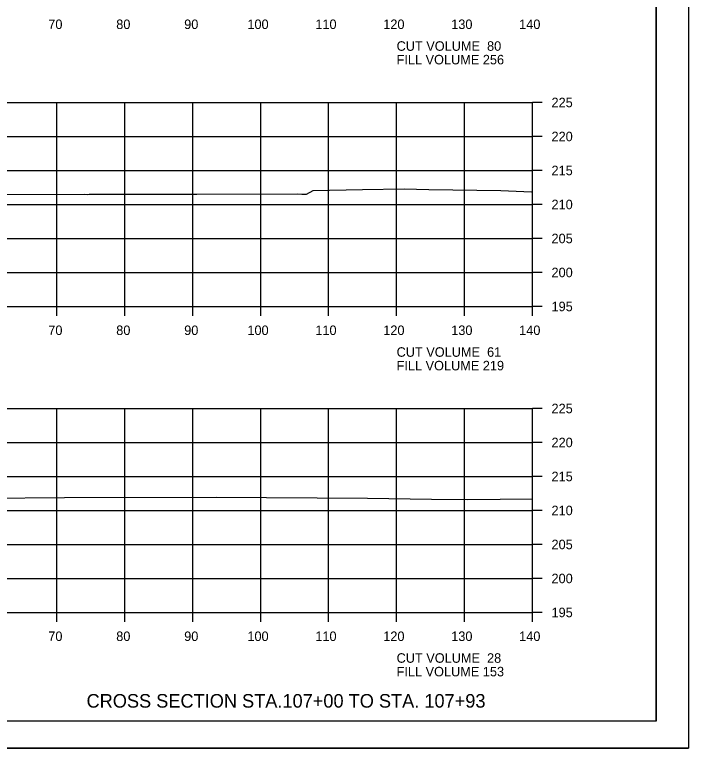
# Model space of a CAD drawing. Extents: x 1368968 to 1369915, y 377395 to 380381.
# Drawn here: x 1369201.9 to 1369301.1, y 379114.4 to 379222.3 of the extents above; entities that cross this region are included whole.
import ezdxf

# ---------------------------------------------------------------- set-up
doc = ezdxf.new("R2010")
doc.units = 0
for name, color, linetype in [('S_BREAKLINE_ANNOT', 7, 'Continuous'), ('S_BRIDGE', 7, 'Continuous'), ('S_BRIDGE_ANNOT', 7, 'Continuous'), ('S_CONTOUR_MINOR', 7, 'Continuous'), ('S_CTL_TABLE', 7, 'Continuous'), ('S_DITCHLINE_ANNOT', 7, 'Continuous'), ('S_DROP_INLET', 7, 'Continuous')]:
    doc.layers.add(name, color=color, linetype=linetype)

msp = doc.modelspace()

# ---------------------------------------------------------------- linework, layer by layer
at = {"layer": 'S_BREAKLINE_ANNOT'}
for p, q in [((1369278.13, 379179.38), (1369278.13, 379209.38)), ((1369279.53, 379209.38), (1369278.13, 379209.38)), ((1369279.53, 379204.38), (1369278.13, 379204.38)), ((1369279.53, 379199.38), (1369278.13, 379199.38)), ((1369279.53, 379194.38), (1369278.13, 379194.38)), ((1369279.53, 379189.38), (1369278.13, 379189.38)), ((1369279.53, 379184.38), (1369278.13, 379184.38)), ((1368998.13, 379179.38), (1369278.13, 379179.38)), ((1369208.13, 379177.98), (1369208.13, 379179.38)), ((1369218.13, 379177.98), (1369218.13, 379179.38)), ((1369228.13, 379177.98), (1369228.13, 379179.38)), ((1369238.13, 379177.98), (1369238.13, 379179.38)), ((1369248.13, 379177.98), (1369248.13, 379179.38)), ((1369258.13, 379177.98), (1369258.13, 379179.38)), ((1369268.13, 379177.98), (1369268.13, 379179.38)), ((1369278.13, 379177.98), (1369278.13, 379179.38)), ((1369279.53, 379179.38), (1369278.13, 379179.38)), ((1369278.13, 379134.38), (1369278.13, 379164.38)), ((1369279.53, 379164.38), (1369278.13, 379164.38)), ((1369279.53, 379159.38), (1369278.13, 379159.38)), ((1369279.53, 379154.38), (1369278.13, 379154.38)), ((1369279.53, 379149.38), (1369278.13, 379149.38)), ((1369279.53, 379144.38), (1369278.13, 379144.38)), ((1369279.53, 379139.38), (1369278.13, 379139.38)), ((1368998.13, 379134.38), (1369278.13, 379134.38)), ((1369208.13, 379132.98), (1369208.13, 379134.38)), ((1369218.13, 379132.98), (1369218.13, 379134.38)), ((1369228.13, 379132.98), (1369228.13, 379134.38)), ((1369238.13, 379132.98), (1369238.13, 379134.38)), ((1369248.13, 379132.98), (1369248.13, 379134.38)), ((1369258.13, 379132.98), (1369258.13, 379134.38)), ((1369268.13, 379132.98), (1369268.13, 379134.38)), ((1369278.13, 379132.98), (1369278.13, 379134.38)), ((1369279.53, 379134.38), (1369278.13, 379134.38))]:
    msp.add_line(p, q, dxfattribs=at)
at = {"layer": 'S_BRIDGE_ANNOT'}
for q in [(1369296.31, 379323.84), (1368980.13, 379118.38)]:
    msp.add_line((1369296.31, 379118.38), q, dxfattribs=at)
at = {"layer": 'S_CTL_TABLE'}
for points in [[(1369196.94, 379195.85), (1369212.19, 379195.88), (1369212.63, 379195.86), (1369212.9, 379195.87), (1369213.23, 379195.88), (1369228.73, 379195.9), (1369243.54, 379195.93), (1369244.16, 379195.9), (1369244.86, 379195.9), (1369245.87, 379196.45), (1369253.1, 379196.56), (1369259.26, 379196.66), (1369262.89, 379196.58), (1369273.47, 379196.41), (1369277.96, 379196.23), (1369278.13, 379196.24)], [(1369197.59, 379151.21), (1369209.27, 379151.28), (1369231.6, 379151.32), (1369253.86, 379151.17), (1369263.27, 379151.05), (1369268.6, 379150.99), (1369278.13, 379151.08)]]:
    msp.add_lwpolyline(points, dxfattribs=at)
at = {"layer": 'S_DITCHLINE_ANNOT'}
for p, q in [((1368998.13, 379209.38), (1369278.13, 379209.38)), ((1369208.13, 379179.38), (1369208.13, 379209.38)), ((1369218.13, 379179.38), (1369218.13, 379209.38)), ((1369228.13, 379179.38), (1369228.13, 379209.38)), ((1369238.13, 379179.38), (1369238.13, 379209.38)), ((1369248.13, 379179.38), (1369248.13, 379209.38)), ((1369258.13, 379179.38), (1369258.13, 379209.38)), ((1369268.13, 379179.38), (1369268.13, 379209.38)), ((1369278.13, 379179.38), (1369278.13, 379209.38)), ((1368998.13, 379204.38), (1369278.13, 379204.38)), ((1368998.13, 379199.38), (1369278.13, 379199.38)), ((1368998.13, 379194.38), (1369278.13, 379194.38)), ((1368998.13, 379189.38), (1369278.13, 379189.38)), ((1368998.13, 379184.38), (1369278.13, 379184.38)), ((1368998.13, 379179.38), (1369278.13, 379179.38)), ((1368998.13, 379164.38), (1369278.13, 379164.38)), ((1369208.13, 379134.38), (1369208.13, 379164.38)), ((1369218.13, 379134.38), (1369218.13, 379164.38)), ((1369228.13, 379134.38), (1369228.13, 379164.38)), ((1369238.13, 379134.38), (1369238.13, 379164.38)), ((1369248.13, 379134.38), (1369248.13, 379164.38)), ((1369258.13, 379134.38), (1369258.13, 379164.38)), ((1369268.13, 379134.38), (1369268.13, 379164.38)), ((1369278.13, 379134.38), (1369278.13, 379164.38)), ((1368998.13, 379159.38), (1369278.13, 379159.38)), ((1368998.13, 379154.38), (1369278.13, 379154.38)), ((1368998.13, 379149.38), (1369278.13, 379149.38)), ((1368998.13, 379144.38), (1369278.13, 379144.38)), ((1368998.13, 379139.38), (1369278.13, 379139.38)), ((1368998.13, 379134.38), (1369278.13, 379134.38))]:
    msp.add_line(p, q, dxfattribs=at)
at = {"layer": 'S_DROP_INLET'}
msp.add_line((1368967.73, 379114.4), (1369301.07, 379114.4), dxfattribs=at)
for points in [[(1368967.73, 379327.74), (1369301.07, 379327.74), (1369301.07, 379114.4), (1368967.73, 379114.4)], [(1369214.05, 379323.84), (1369214.05, 379313.96), (1369249.79, 379313.96), (1369249.79, 379311.04), (1369272.99, 379311.04), (1369272.99, 379286.71), (1369296.31, 379286.71), (1369296.31, 379118.38), (1368980.13, 379118.38), (1368980.13, 379323.84)]]:
    msp.add_lwpolyline(points, close=True, dxfattribs=at)

# ---------------------------------------------------------------- texts
at = {"layer": 'S_BRIDGE'}
for s, p in [('70', (1369206.87, 379220.18)), ('80', (1369216.87, 379220.18)), ('90', (1369226.87, 379220.18)), ('100', (1369236.17, 379220.18)), ('110', (1369246.17, 379220.18)), ('120', (1369256.17, 379220.18)), ('130', (1369266.17, 379220.18)), ('140', (1369276.17, 379220.18)), ('CUT VOLUME  80', (1369258.13, 379216.98)), ('FILL VOLUME 256', (1369258.13, 379214.98)), ('225', (1369280.93, 379208.68)), ('220', (1369280.93, 379203.68)), ('215', (1369280.93, 379198.68)), ('210', (1369280.93, 379193.68)), ('205', (1369280.93, 379188.68)), ('200', (1369280.93, 379183.68)), ('195', (1369280.93, 379178.68)), ('70', (1369206.87, 379175.18)), ('80', (1369216.87, 379175.18)), ('90', (1369226.87, 379175.18)), ('100', (1369236.17, 379175.18)), ('110', (1369246.17, 379175.18)), ('120', (1369256.17, 379175.18)), ('130', (1369266.17, 379175.18)), ('140', (1369276.17, 379175.18)), ('CUT VOLUME  61', (1369258.13, 379171.98)), ('FILL VOLUME 219', (1369258.13, 379169.98)), ('225', (1369280.93, 379163.68)), ('220', (1369280.93, 379158.68)), ('215', (1369280.93, 379153.68)), ('210', (1369280.93, 379148.68)), ('205', (1369280.93, 379143.68)), ('200', (1369280.93, 379138.68)), ('195', (1369280.93, 379133.68)), ('70', (1369206.87, 379130.18)), ('80', (1369216.87, 379130.18)), ('90', (1369226.87, 379130.18)), ('100', (1369236.17, 379130.18)), ('110', (1369246.17, 379130.18)), ('120', (1369256.17, 379130.18)), ('130', (1369266.17, 379130.18)), ('140', (1369276.17, 379130.18)), ('CUT VOLUME  28', (1369258.13, 379126.98)), ('FILL VOLUME 153', (1369258.13, 379124.98))]:
    msp.add_text(s, height=1.4, dxfattribs=at).set_placement(p)
at = {"layer": 'S_CONTOUR_MINOR'}
msp.add_text('CROSS SECTION STA.107+00 TO STA. 107+93', height=2, dxfattribs=at).set_placement((1369212.5, 379120.38))

doc.saveas('drawing.dxf')
